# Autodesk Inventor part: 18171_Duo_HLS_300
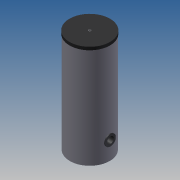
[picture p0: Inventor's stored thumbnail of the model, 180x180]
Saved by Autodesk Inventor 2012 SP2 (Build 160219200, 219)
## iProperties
allow_slope_adjustment: 0 ul
connection_type: 13 ul
flow_configuration2: 1 ul
flow_direction: 2 ul
loss_method: 0 ul
radius: 19,625 mm
radius: 12,250 mm
radius: 15,375 mm
Created: 2014-05
Part Number: 18171_Duo_HLS_300
Material: Default
Document SubType Name: Modeling
Designer: michel
Density: 1 g/cm^3
description: 0:0:18171_Duo_HLS_300
manufacturer: 0:0:Flamco Group
model: 0:0:Duo HLS 300
url: 0:0:www.flamcogroup.com
Author: michel
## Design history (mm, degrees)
sketch "Sketch1"
  geometry: C1 r 330 at (0, 0); 1 further point
  constraints: 1 centre point, 1 coincident
  dimensions: "d0" = 660 diameter of C1
extrude "Extrusion1" new body sketch "Sketch1" distance "d1" = 1710; taper "d2" = 0 deg
sketch "Sketch2"
  geometry: L1 (-330, 1710)-(330, 1710) reference; L2 (-330, 0)-(330, 0) reference; L3 (-330, 0)-(-330, 1710) reference; L4 (0, -390)-(0, 2340) reference; L5 (-504, 65)-(536, 65); L6 (-504, 305)-(536, 305); L7 (-490, 845)-(536, 845); L8 (-490, 945)-(536, 945); L9 (-490, 1560)-(536, 1560); L10 (330, 65)-(290, 65); L11 (290, 65)-(290, 81.625); L12 (290, 81.625)-(330, 81.625); L13 (330, 81.625)-(330, 65); L14 (290, 48.375)-(331, 48.375); L15 (331, 48.375)-(331, 49.625); L16 (331, 49.625)-(290, 49.625); L17 (290, 49.625)-(290, 48.375); L18 (330, 305)-(290, 305); L19 (290, 305)-(290, 325.955); L20 (290, 325.955)-(330, 325.955); L21 (330, 325.955)-(330, 305); L22 (290, 284.045)-(331, 284.045); L23 (331, 284.045)-(331, 285.375); L24 (331, 285.375)-(290, 285.375); L25 (290, 285.375)-(290, 284.045); L26 (330, 845)-(290, 845); L27 (290, 845)-(290, 858.22); L28 (290, 858.22)-(330, 858.22); L29 (330, 858.22)-(330, 845); L30 (290, 832.75)-(331, 832.75); L31 (331, 832.75)-(331, 831.78); L32 (331, 831.78)-(290, 831.78); L33 (290, 831.78)-(290, 832.75); L34 (330, 945)-(290, 945); L35 (290, 945)-(290, 965.955); L36 (290, 965.955)-(330, 965.955); L37 (330, 965.955)-(330, 945); L38 (290, 924.045)-(331, 924.045); L39 (331, 924.045)-(331, 925.375); L40 (331, 925.375)-(290, 925.375); L41 (290, 925.375)-(290, 924.045); L42 (330, 1560)-(290, 1560); L43 (290, 1560)-(290, 1576.625); L44 (290, 1576.625)-(330, 1576.625); L45 (330, 1576.625)-(330, 1560); L46 (290, 1543.375)-(331, 1543.375); L47 (331, 1543.375)-(331, 1544.625); L48 (331, 1544.625)-(290, 1544.625); L49 (290, 1544.625)-(290, 1543.375); L50 (0, 305)-(-504, 305); L51 (-330, 305)-(-342.5, 305); L52 (-342.5, 305)-(-342.5, 395); L53 (-342.5, 395)-(-330, 395); L54 (-330, 395)-(-330, 305); L55 (330, 1710)-(335, 1710); L56 (335, 1710)-(335, 1660); L57 (335, 1660)-(330, 1660); L58 (330, 1660)-(330, 1710); 2 further points
  constraints: 108 end point, 28 parallel, 13 perpendicular, 12 horizontal, 8 point on line, 6 other
  dimensions: "d6" = 65 distance from line of point (0, 0) L5; "d7" = 305 distance from line of point (0, 0) L6; "d8" = 845 distance from line of point (0, 0) L7; "d9" = 945 distance between parallel lines of L2 L8; "d10" = 1560 distance from line of point (0, 0) L9; "d15" = 16.625 distance of L10.end L11.end; "d16" = 16.625 distance between parallel lines of L5 L12 (derived); "d17" = 16.625 distance between parallel lines of L14 L5 (= d15); "d18" = 1.25 distance between parallel lines of L16 L14 (computed from d16); "d19" = 1 dimension on L15; "d22" = 40 distance from line of L12.end L11; "d23" = 41 distance from line of L14.end L17; "d24" = 20.955 distance of L18.end L19.end; "d25" = 40 distance from line of L20.end L19; "d26" = 20.955 distance between parallel lines of L6 L20 (derived); "d27" = 20.955 distance between parallel lines of L6 L22 (= d24); "d28" = 1.33 distance between parallel lines of L24 L22 (computed from d24); "d29" = 1 dimension on L23; "d30" = 41 distance between parallel lines of L23 L25; "d33" = 13.22 distance of L26.end L27.end; "d34" = 13.22 distance between parallel lines of L7 L28 (derived); "d35" = 40 dimension on L27; "d37" = 0.97 distance between parallel lines of L32 L30 (computed from d34); "d38" = 1 dimension on L31; "d39" = 41 distance between parallel lines of L31 L33; "d42" = 20.955 distance of L34.end L35.end; "d43" = 20.955 distance between parallel lines of L8 L36 (derived); "d44" = 40 distance from line of L36.end L35; "d45" = 20.955 distance between parallel lines of L38 L8 (= d42); "d46" = 1.33 distance between parallel lines of L40 L38 (computed from d42); "d47" = 1 dimension on L39; "d48" = 41 distance between parallel lines of L39 L41; "d49" = 16.625 distance of L42.end L43.end; "d50" = 40 distance from line of L44.end L43; "d51" = 16.625 distance between parallel lines of L9 L44 (derived); "d52" = 16.625 distance between parallel lines of L46 L9 (= d49); "d53" = 1.25 distance between parallel lines of L48 L46 (computed from d49); "d54" = 1 dimension on L47; "d55" = 41 distance between parallel lines of L47 L49; "d80" = 305 distance from line of point (0, 0) L50; "d81" = 12.5 distance of L52.end L53.end; "d82" = 90 distance of L51.end L52.end; "d83" = 90 distance between parallel lines of L50 L53 (derived); "d109" = 13.22 distance between parallel lines of L7 L32 (= d33); "d110" = 5 distance of L56.end L57.end; "d111" = 50 distance of L55.end L56.end
  node "Projected Loop1"
revolve "Revolution1" stored, may be unused: angle "d5" = 90 deg
revolve "Revolution2" stored, may be unused: angle "d20" = 90 deg
revolve "Revolution3" stored, may be unused: angle "d21" = 90 deg
revolve "Revolution4" stored, may be unused: angle "d31" = 90 deg
revolve "Revolution5" stored, may be unused: angle "d32" = 90 deg
revolve "Revolution6" stored, may be unused: angle "d40" = 90 deg
revolve "Revolution7" stored, may be unused: angle "d41" = 90 deg
revolve "Revolution8" stored, may be unused: angle "d72" = 90 deg
revolve "Revolution9" stored, may be unused: angle "d73" = 90 deg
revolve "Revolution10" stored, may be unused: angle "d74" = 90 deg
revolve "Revolution11" stored, may be unused: angle "d75" = 90 deg
revolve "Revolution16" stored, may be unused: angle "d84" = 90 deg
sketch "Sketch3"
  geometry: C1 r 62.5 at (0, 0); A1 r 90 centre (0, 0) between (90, 0) and (-90, 0) reference; 1 further point
  constraints: 1 centre point, 1 coincident
  dimensions: "d85" = 125 diameter of C1
extrude "Extrusion2" join sketch "Sketch3" stored distance "d86" = 1450; taper "d87" = 0 deg
sketch "Sketch4"
  geometry: C1 r 90 at (0, 0) reference; C2 r 55 at (0, 0); 1 further point
  constraints: 1 centre point, 1 coincident
  dimensions: "d88" = 110 diameter of C2
extrude "Extrusion3" cut sketch "Sketch4" distance "d89" = 80; taper "d90" = 0 deg
workplane "Work Plane1"
sketch "Sketch6"
  geometry: C1 r 335 at (0, 0) reference; C2 r 20.955 at (0, 0); C3 r 19.625 at (0, 0)
  constraints: 2 centre point, 2 coincident
  dimensions: "d103" = 41.91 diameter of C2; "d104" = 39.25 diameter of C3
extrude "Extrusion4" cut sketch "Sketch6" distance "d105" = 40; taper "d106" = 0 deg
extrude "Extrusion5" join sketch "Sketch6" distance "d107" = 2; taper "d108" = 0 deg
body "Solid1"
other parameters: "d91" = 45 deg
